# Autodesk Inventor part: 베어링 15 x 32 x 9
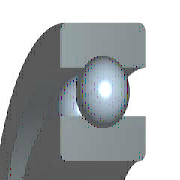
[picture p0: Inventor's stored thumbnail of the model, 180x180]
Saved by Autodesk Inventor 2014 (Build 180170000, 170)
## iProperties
Created: 2012-02
Part Number: 베어링 15 x 32 x 9
Material: 강철, 연강
Description: 깊은 그루브 볼 베어링
Document SubType Name: Modeling
Standard: KS B 2023
Designer: mduedu
Standards Organization: KS
Language: ko-KR
Size Designation: 6002 - 15 x 32 x 9
Categories: <MemberInstance><Categories><Category DisplayName="샤프트 부품" InternalName="7f7aeb1f-a693-4053-b835-cee3144e0d98" Mnemonic="SHFT"><Category DisplayName="베어링" Inter
Density: 1 g/cm^3
Appearance: 강철
IsCustomPart: 0
Author: mduedu
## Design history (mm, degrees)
sketch "스케치" dims "d0" = 4.42 (= -0.26 x WD + 0.26 x BD)
  geometry: L1 (2.29, 11.75)-(6.71, 11.75); L2 (4.5, 11.75)-(4.5, 9.54); L3 (4.5, 11.75)-(4.5, 13.96); L4 (2.858, 10.271)-(0, 10.271); L5 (0, 7.5)-(9, 7.5); L6 (2.858, 13.229)-(0, 13.229); L7 (0, 16)-(9, 16); L8 (9, 7.5)-(9, 10.271); L9 (6.142, 10.271)-(9, 10.271); L10 (6.142, 13.229)-(9, 13.229); L11 (9, 16)-(9, 13.229); L12 (-1.4, 0)-(8.4, 0) reference; L13 (0, -0.3)-(0, 5.3) reference
  constraints: 22 end point, 4 point on line, 2 collinear, 2 perpendicular, 2 symmetric about line, 1 midpoint, 1 parallel, 14 other
  dimensions: "d9" = 15 diameter of L5 L12 (= WD); "d11" = 32 diameter of L7 L12 (= BD); "d12" = 9 distance between parallel lines of L8 L13 (= KB); "d13" = 20.542 diameter of L9 L12 (= 0.326 x BD + 0.674 x WD)
revolve "본체" stored, may be unused: angle "d6" = 90 deg
revolve "볼" stored, may be unused: angle "d7" = 90 deg
pattern_circular "IDS_ARRAYBALL[SIMPL:T]" dims angle "d3" = 360 deg
body "Solid1"
fillet "모깎기1" dims "d1" = 0.3 (= KRS)
other parameters: "WD" = 15 [user parameter; used in 5 equation terms], "BD" = 32 [user parameter; used in 5 equation terms], "KB" = 9 [user parameter; used in 1 equation term], "KRS" = 0.3 [user parameter; used in 1 equation term], "d4" = 0, "d5" = 0, "d8" = 0, "d14" = 0, "d15" = 0, "BBA" = 0 [user parameter], "BC0" = 2850000 [user parameter], "BC" = 5590000 [user parameter], "BR" = 16 (= 0.5 x BD) [user parameter], "WR" = 7.5 (= 0.5 x WD) [user parameter]
